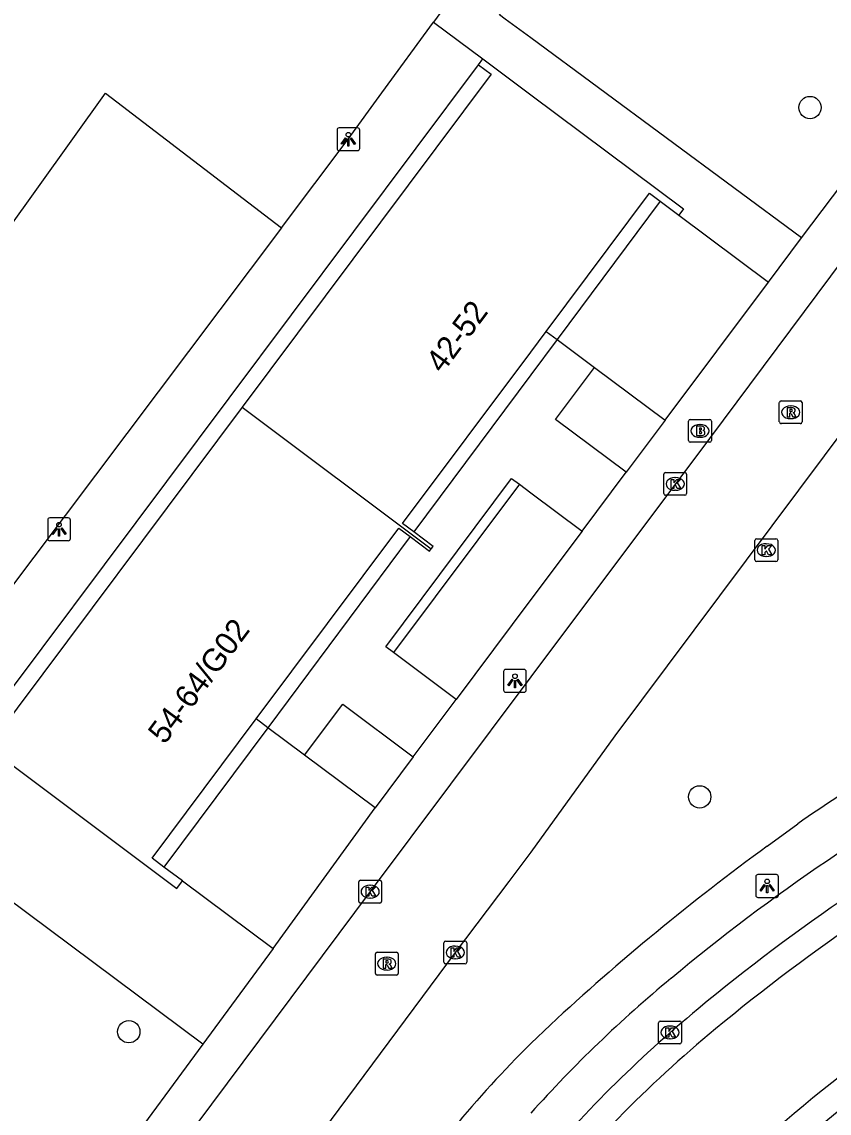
# Model space of a CAD drawing. Extents: x 160026 to 161302, y 384757 to 385701.
# Drawn here: x 160477.69 to 160513.08, y 385187.88 to 385235.75 of the extents above; entities that cross this region are included whole.
import ezdxf

# ---------------------------------------------------------------- set-up
doc = ezdxf.new("R2010")
doc.units = 0
for name, color, linetype in [('IMGEO_Boom', 7, 'Continuous'), ('IMGEO_Brandkraan', 7, 'Continuous'), ('IMGEO_Groenvoorziening', 7, 'Continuous'), ('IMGEO_Haag', 7, 'Continuous'), ('IMGEO_Kolk', 7, 'Continuous'), ('IMGEO_Lichtpunt', 7, 'Continuous'), ('IMGEO_Pand', 7, 'Continuous'), ('IMGEO_Pand_nummerreeks', 7, 'Continuous'), ('IMGEO_Rijbaan_lokaal_open', 7, 'Continuous'), ('IMGEO_Rioolput', 7, 'Continuous'), ('IMGEO_Voetpad_open', 7, 'Continuous')]:
    doc.layers.add(name, color=color, linetype=linetype)

msp = doc.modelspace()

# ---------------------------------------------------------------- linework, layer by layer
at = {"layer": 'IMGEO_Boom'}
for centre in [(160512.24, 385231.991), (160507.406, 385201.754), (160482.378, 385191.451)]:
    msp.add_circle(centre, 0.489, dxfattribs=at)
at = {"layer": 'IMGEO_Brandkraan'}
for p, q in [((160506.992, 385218.308), (160507.844, 385218.308)), ((160506.917, 385217.382), (160506.917, 385218.234)), ((160507.405, 385218.088), (160507.43, 385218.088)), ((160507.918, 385218.234), (160507.918, 385217.382)), ((160507.844, 385217.308), (160506.992, 385217.308)), ((160507.428, 385217.528), (160507.403, 385217.528))]:
    msp.add_line(p, q, dxfattribs=at)
for points in [[(160506.992, 385218.308), (160507.844, 385218.308)], [(160506.917, 385217.382), (160506.917, 385218.234)], [(160507.265, 385218.008), (160507.265, 385217.608), (160507.478, 385217.608)], [(160507.496, 385218.008), (160507.265, 385218.008)], [(160507.444, 385217.927), (160507.39, 385217.927), (160507.39, 385217.851)], [(160507.39, 385217.851), (160507.443, 385217.851)], [(160507.918, 385218.234), (160507.918, 385217.382)], [(160507.844, 385217.308), (160506.992, 385217.308)], [(160507.452, 385217.775), (160507.39, 385217.775), (160507.39, 385217.694)], [(160507.39, 385217.694), (160507.452, 385217.694)]]:
    msp.add_lwpolyline(points, dxfattribs=at)
for centre, radius, start, end in [((160506.994, 385218.232), 0.0765, 91.552, 178.448), ((160506.994, 385218.232), 0.0765, 91.552, 178.448), ((160507.842, 385218.232), 0.0765, 1.552, 88.448), ((160507.842, 385218.232), 0.0765, 1.552, 88.448), ((160507.445, 385217.889), 0.0379, 267.8285, 90.9355), ((160507.5, 385217.863), 0.145, 59.4692, 91.5367), ((160507.525, 385217.91), 0.0922, 285.5137, 58.1501), ((160507.53, 385217.718), 0.105, 301.3115, 78.989), ((160506.994, 385217.384), 0.0765, 181.552, 268.448), ((160506.994, 385217.384), 0.0765, 181.552, 268.448), ((160507.453, 385217.734), 0.0404, 269.8759, 90.5077), ((160507.484, 385217.859), 0.251, 268.6676, 293.5347), ((160507.842, 385217.384), 0.0765, 271.552, 358.448), ((160507.842, 385217.384), 0.0765, 271.552, 358.448)]:
    msp.add_arc(centre, radius, start, end, dxfattribs=at)
for centre, major_axis, ratio, start_param, end_param in [((160507.404, 385217.808), (-0.387, 0.002), 0.722429, 4.712389, 7.853982), ((160507.429, 385217.808), (-0.39, 0.002), 0.717154, 1.570796, 4.712389)]:
    msp.add_ellipse(centre, major_axis=major_axis, ratio=ratio, start_param=start_param, end_param=end_param, dxfattribs=at)
at = {"layer": 'IMGEO_Groenvoorziening'}
msp.add_lwpolyline([(160468.159, 385214.178), (160481.35, 385232.629), (160489.078, 385226.722)], dxfattribs=at)
at = {"layer": 'IMGEO_Haag'}
for points in [[(160499.5, 385215.467), (160493.98, 385208.083)], [(160485.617, 385190.899), (160475.997, 385198.091), (160474.75, 385196.469)]]:
    msp.add_lwpolyline(points, dxfattribs=at)
at = {"layer": 'IMGEO_Kolk'}
for p, q in [((160505.83, 385215.056), (160505.83, 385215.908)), ((160505.905, 385215.982), (160506.757, 385215.982)), ((160506.831, 385215.908), (160506.831, 385215.056)), ((160506.318, 385215.762), (160506.343, 385215.762)), ((160506.757, 385214.982), (160505.905, 385214.982)), ((160506.341, 385215.202), (160506.316, 385215.202)), ((160509.822, 385212.15), (160509.822, 385213.002)), ((160509.897, 385213.076), (160510.749, 385213.076)), ((160510.823, 385213.002), (160510.823, 385212.15)), ((160510.31, 385212.856), (160510.335, 385212.856)), ((160510.749, 385212.076), (160509.897, 385212.076)), ((160510.333, 385212.296), (160510.308, 385212.296)), ((160492.458, 385197.168), (160492.458, 385198.02)), ((160492.533, 385198.094), (160493.385, 385198.094)), ((160492.946, 385197.874), (160492.971, 385197.874)), ((160493.459, 385198.02), (160493.459, 385197.168)), ((160492.969, 385197.314), (160492.944, 385197.314)), ((160493.385, 385197.094), (160492.533, 385197.094)), ((160496.189, 385194.502), (160496.189, 385195.354)), ((160496.264, 385195.428), (160497.116, 385195.428)), ((160497.19, 385195.354), (160497.19, 385194.502)), ((160496.677, 385195.208), (160496.702, 385195.208)), ((160497.116, 385194.428), (160496.264, 385194.428)), ((160496.7, 385194.648), (160496.675, 385194.648)), ((160505.601, 385190.993), (160505.601, 385191.845)), ((160505.676, 385191.919), (160506.528, 385191.919)), ((160506.089, 385191.699), (160506.114, 385191.699)), ((160506.602, 385191.845), (160506.602, 385190.993)), ((160506.112, 385191.139), (160506.087, 385191.139)), ((160506.528, 385190.919), (160505.676, 385190.919))]:
    msp.add_line(p, q, dxfattribs=at)
for points in [[(160505.83, 385215.056), (160505.83, 385215.908)], [(160505.905, 385215.982), (160506.757, 385215.982)], [(160506.831, 385215.908), (160506.831, 385215.056)], [(160506.151, 385215.682), (160506.274, 385215.682), (160506.274, 385215.531), (160506.404, 385215.682), (160506.568, 385215.682), (160506.422, 385215.531), (160506.575, 385215.282), (160506.423, 385215.282), (160506.338, 385215.446), (160506.274, 385215.379), (160506.274, 385215.282), (160506.151, 385215.282), (160506.151, 385215.682)], [(160506.757, 385214.982), (160505.905, 385214.982)], [(160509.822, 385212.15), (160509.822, 385213.002)], [(160509.897, 385213.076), (160510.749, 385213.076)], [(160510.823, 385213.002), (160510.823, 385212.15)], [(160510.143, 385212.776), (160510.266, 385212.776), (160510.266, 385212.625), (160510.396, 385212.776), (160510.56, 385212.776), (160510.414, 385212.625), (160510.567, 385212.376), (160510.415, 385212.376), (160510.33, 385212.54), (160510.266, 385212.473), (160510.266, 385212.376), (160510.143, 385212.376), (160510.143, 385212.776)], [(160510.749, 385212.076), (160509.897, 385212.076)], [(160492.458, 385197.168), (160492.458, 385198.02)], [(160492.533, 385198.094), (160493.385, 385198.094)], [(160492.779, 385197.794), (160492.902, 385197.794), (160492.902, 385197.643), (160493.032, 385197.794), (160493.196, 385197.794), (160493.05, 385197.643), (160493.203, 385197.394), (160493.051, 385197.394), (160492.966, 385197.558), (160492.902, 385197.491), (160492.902, 385197.394), (160492.779, 385197.394), (160492.779, 385197.794)], [(160493.459, 385198.02), (160493.459, 385197.168)], [(160493.385, 385197.094), (160492.533, 385197.094)], [(160496.189, 385194.502), (160496.189, 385195.354)], [(160496.264, 385195.428), (160497.116, 385195.428)], [(160497.19, 385195.354), (160497.19, 385194.502)], [(160496.51, 385195.128), (160496.633, 385195.128), (160496.633, 385194.977), (160496.763, 385195.128), (160496.927, 385195.128), (160496.781, 385194.977), (160496.934, 385194.728), (160496.782, 385194.728), (160496.697, 385194.892), (160496.633, 385194.825), (160496.633, 385194.728), (160496.51, 385194.728), (160496.51, 385195.128)], [(160497.116, 385194.428), (160496.264, 385194.428)], [(160505.601, 385190.993), (160505.601, 385191.845)], [(160505.676, 385191.919), (160506.528, 385191.919)], [(160505.922, 385191.619), (160506.045, 385191.619), (160506.045, 385191.468), (160506.175, 385191.619), (160506.339, 385191.619), (160506.193, 385191.468), (160506.346, 385191.219), (160506.194, 385191.219), (160506.109, 385191.383), (160506.045, 385191.316), (160506.045, 385191.219), (160505.922, 385191.219), (160505.922, 385191.619)], [(160506.602, 385191.845), (160506.602, 385190.993)], [(160506.528, 385190.919), (160505.676, 385190.919)]]:
    msp.add_lwpolyline(points, dxfattribs=at)
for centre, start, end in [((160505.907, 385215.906), 91.552, 178.448), ((160505.907, 385215.906), 91.552, 178.448), ((160506.755, 385215.906), 1.552, 88.448), ((160506.755, 385215.906), 1.552, 88.448), ((160505.907, 385215.058), 181.552, 268.448), ((160505.907, 385215.058), 181.552, 268.448), ((160506.755, 385215.058), 271.552, 358.448), ((160506.755, 385215.058), 271.552, 358.448), ((160509.899, 385213), 91.552, 178.448), ((160509.899, 385213), 91.552, 178.448), ((160510.747, 385213), 1.552, 88.448), ((160510.747, 385213), 1.552, 88.448), ((160509.899, 385212.152), 181.552, 268.448), ((160509.899, 385212.152), 181.552, 268.448), ((160510.747, 385212.152), 271.552, 358.448), ((160510.747, 385212.152), 271.552, 358.448), ((160492.535, 385198.018), 91.552, 178.448), ((160492.535, 385198.018), 91.552, 178.448), ((160493.383, 385198.018), 1.552, 88.448), ((160493.383, 385198.018), 1.552, 88.448), ((160492.535, 385197.17), 181.552, 268.448), ((160492.535, 385197.17), 181.552, 268.448), ((160493.383, 385197.17), 271.552, 358.448), ((160493.383, 385197.17), 271.552, 358.448), ((160496.266, 385195.352), 91.552, 178.448), ((160496.266, 385195.352), 91.552, 178.448), ((160497.114, 385195.352), 1.552, 88.448), ((160497.114, 385195.352), 1.552, 88.448), ((160496.266, 385194.504), 181.552, 268.448), ((160496.266, 385194.504), 181.552, 268.448), ((160497.114, 385194.504), 271.552, 358.448), ((160497.114, 385194.504), 271.552, 358.448), ((160505.678, 385191.843), 91.552, 178.448), ((160505.678, 385191.843), 91.552, 178.448), ((160506.526, 385191.843), 1.552, 88.448), ((160506.526, 385191.843), 1.552, 88.448), ((160505.678, 385190.995), 181.552, 268.448), ((160505.678, 385190.995), 181.552, 268.448), ((160506.526, 385190.995), 271.552, 358.448), ((160506.526, 385190.995), 271.552, 358.448)]:
    msp.add_arc(centre, 0.0765, start, end, dxfattribs=at)
for centre, major_axis, ratio, start_param, end_param in [((160506.317, 385215.482), (-0.387, 0.002), 0.722429, 4.712389, 7.853982), ((160506.342, 385215.482), (-0.39, 0.002), 0.717154, 1.570796, 4.712389), ((160510.309, 385212.576), (-0.387, 0.002), 0.722429, 4.712389, 7.853982), ((160510.334, 385212.576), (-0.39, 0.002), 0.717154, 1.570796, 4.712389), ((160492.945, 385197.594), (-0.387, 0.002), 0.722429, 4.712389, 7.853982), ((160492.97, 385197.594), (-0.39, 0.002), 0.717154, 1.570796, 4.712389), ((160496.676, 385194.928), (-0.387, 0.002), 0.722429, 4.712389, 7.853982), ((160496.701, 385194.928), (-0.39, 0.002), 0.717154, 1.570796, 4.712389), ((160506.088, 385191.419), (-0.387, 0.002), 0.722429, 4.712389, 7.853982), ((160506.113, 385191.419), (-0.39, 0.002), 0.717154, 1.570796, 4.712389)]:
    msp.add_ellipse(centre, major_axis=major_axis, ratio=ratio, start_param=start_param, end_param=end_param, dxfattribs=at)
at = {"layer": 'IMGEO_Lichtpunt'}
for p, q in [((160491.506, 385231.005), (160491.506, 385230.198)), ((160491.506, 385231.005), (160491.506, 385230.198)), ((160492.408, 385231.1), (160491.6, 385231.1)), ((160492.408, 385231.1), (160491.6, 385231.1)), ((160492.502, 385230.198), (160492.502, 385231.005)), ((160492.502, 385230.198), (160492.502, 385231.005)), ((160491.6, 385230.104), (160492.408, 385230.104)), ((160491.6, 385230.104), (160492.408, 385230.104)), ((160479.724, 385213.989), (160478.916, 385213.989)), ((160479.724, 385213.989), (160478.916, 385213.989)), ((160478.822, 385213.894), (160478.822, 385213.087)), ((160478.822, 385213.894), (160478.822, 385213.087)), ((160479.818, 385213.087), (160479.818, 385213.894)), ((160479.818, 385213.087), (160479.818, 385213.894)), ((160478.916, 385212.993), (160479.724, 385212.993)), ((160478.916, 385212.993), (160479.724, 385212.993)), ((160499.708, 385207.342), (160498.9, 385207.342)), ((160499.708, 385207.342), (160498.9, 385207.342)), ((160498.806, 385207.247), (160498.806, 385206.44)), ((160498.806, 385207.247), (160498.806, 385206.44)), ((160499.802, 385206.44), (160499.802, 385207.247)), ((160499.802, 385206.44), (160499.802, 385207.247)), ((160498.9, 385206.346), (160499.708, 385206.346)), ((160498.9, 385206.346), (160499.708, 385206.346)), ((160509.862, 385198.248), (160509.862, 385197.441)), ((160509.862, 385198.248), (160509.862, 385197.441)), ((160510.764, 385198.343), (160509.956, 385198.343)), ((160510.764, 385198.343), (160509.956, 385198.343)), ((160510.858, 385197.441), (160510.858, 385198.248)), ((160510.858, 385197.441), (160510.858, 385198.248)), ((160509.956, 385197.347), (160510.764, 385197.347)), ((160509.956, 385197.347), (160510.764, 385197.347))]:
    msp.add_line(p, q, dxfattribs=at)
for points in [[(160491.88, 385230.669), (160491.919, 385230.641), (160491.731, 385230.379), (160491.693, 385230.406), (160491.88, 385230.669)], [(160491.982, 385230.621), (160492.029, 385230.621), (160492.029, 385230.299), (160491.982, 385230.299), (160491.982, 385230.621)], [(160492.092, 385230.641), (160492.13, 385230.668), (160492.317, 385230.406), (160492.278, 385230.378), (160492.092, 385230.641)], [(160479.196, 385213.558), (160479.235, 385213.53), (160479.047, 385213.268), (160479.009, 385213.295), (160479.196, 385213.558)], [(160479.298, 385213.51), (160479.345, 385213.51), (160479.345, 385213.188), (160479.298, 385213.188), (160479.298, 385213.51)], [(160479.408, 385213.53), (160479.446, 385213.557), (160479.633, 385213.295), (160479.594, 385213.267), (160479.408, 385213.53)], [(160499.18, 385206.911), (160499.219, 385206.883), (160499.031, 385206.621), (160498.993, 385206.648), (160499.18, 385206.911)], [(160499.282, 385206.863), (160499.329, 385206.863), (160499.329, 385206.541), (160499.282, 385206.541), (160499.282, 385206.863)], [(160499.392, 385206.883), (160499.43, 385206.91), (160499.617, 385206.648), (160499.578, 385206.62), (160499.392, 385206.883)], [(160510.236, 385197.912), (160510.275, 385197.884), (160510.087, 385197.622), (160510.049, 385197.649), (160510.236, 385197.912)], [(160510.338, 385197.864), (160510.385, 385197.864), (160510.385, 385197.542), (160510.338, 385197.542), (160510.338, 385197.864)], [(160510.448, 385197.884), (160510.486, 385197.911), (160510.673, 385197.649), (160510.634, 385197.621), (160510.448, 385197.884)]]:
    msp.add_lwpolyline(points, dxfattribs=at)
for centre in [(160492.005, 385230.803), (160479.321, 385213.692), (160499.305, 385207.045), (160510.361, 385198.046)]:
    msp.add_circle(centre, 0.0994, dxfattribs=at)
for centre, start, end in [((160491.6, 385231.005), 90, 180), ((160491.6, 385231.005), 90, 180), ((160492.408, 385231.005), 0, 90), ((160492.408, 385231.005), 0, 90), ((160491.6, 385230.198), 180, 270), ((160491.6, 385230.198), 180, 270), ((160492.408, 385230.198), 270, 0), ((160492.408, 385230.198), 270, 360), ((160478.916, 385213.894), 90, 180), ((160478.916, 385213.894), 90, 180), ((160479.724, 385213.894), 0, 90), ((160479.724, 385213.894), 0, 90), ((160478.916, 385213.087), 180, 270), ((160478.916, 385213.087), 180, 270), ((160479.724, 385213.087), 270, 0), ((160479.724, 385213.087), 270, 360), ((160498.9, 385207.247), 90, 180), ((160498.9, 385207.247), 90, 180), ((160499.708, 385207.247), 0, 90), ((160499.708, 385207.247), 0, 90), ((160498.9, 385206.44), 180, 270), ((160498.9, 385206.44), 180, 270), ((160499.708, 385206.44), 270, 0), ((160499.708, 385206.44), 270, 360), ((160509.956, 385198.248), 90, 180), ((160509.956, 385198.248), 90, 180), ((160510.764, 385198.248), 0, 90), ((160510.764, 385198.248), 0, 90), ((160509.956, 385197.441), 180, 270), ((160509.956, 385197.441), 180, 270), ((160510.764, 385197.441), 270, 0), ((160510.764, 385197.441), 270, 360)]:
    msp.add_arc(centre, 0.0946, start, end, dxfattribs=at)
at = {"layer": 'IMGEO_Pand'}
for points in [[(160497.703, 385233.866), (160497.896, 385234.123)], [(160497.896, 385234.123), (160500, 385232.551), (160506.692, 385227.547), (160506.486, 385227.271)], [(160497.703, 385233.866), (160498.26, 385233.45), (160487.341, 385218.845)], [(160500.676, 385222.173), (160505.205, 385228.229), (160505.665, 385227.885)], [(160505.665, 385227.885), (160506.486, 385227.271)], [(160494.866, 385213.374), (160494.374, 385213.742), (160500, 385221.268), (160500.676, 385222.173)], [(160487.341, 385218.845), (160476.395, 385204.204), (160475.837, 385204.622)], [(160487.341, 385218.845), (160495.64, 385212.639)], [(160487.957, 385205.171), (160494.218, 385213.546), (160494.717, 385213.173)], [(160494.717, 385213.173), (160495.565, 385212.539), (160495.64, 385212.639)], [(160495.64, 385212.639), (160495.715, 385212.74), (160494.866, 385213.374)], [(160483.921, 385198.677), (160483.396, 385199.07), (160487.957, 385205.171)], [(160475.636, 385204.353), (160484.481, 385197.741), (160484.729, 385198.073)], [(160484.729, 385198.073), (160483.921, 385198.677)]]:
    msp.add_lwpolyline(points, dxfattribs=at)
at = {"layer": 'IMGEO_Rijbaan_lokaal_open'}
for points in [[(160534.696, 385253.556), (160532.047, 385250), (160507.827, 385217.481), (160500, 385207.013), (160492.96, 385197.597), (160479.05, 385178.94), (160478.747, 385178.564)], [(160505.665, 385227.885), (160501.15, 385221.819)], [(160506.486, 385227.271), (160510.414, 385224.335)], [(160505.886, 385218.278), (160510.414, 385224.335)], [(160500.676, 385222.173), (160501.15, 385221.819)], [(160501.15, 385221.819), (160502.798, 385220.586)], [(160515.782, 385220.64), (160514.031, 385218.275), (160503.68, 385204.434), (160500, 385199.324), (160499.031, 385198.037), (160496.692, 385194.932), (160483.238, 385176.808)], [(160502.798, 385220.586), (160505.886, 385218.278)], [(160488.471, 385204.787), (160487.957, 385205.171)], [(160488.471, 385204.787), (160483.921, 385198.677)], [(160490.085, 385203.58), (160488.471, 385204.787)], [(160493.173, 385201.272), (160490.085, 385203.58)], [(160488.705, 385195.106), (160493.173, 385201.272)], [(160484.729, 385198.073), (160488.705, 385195.106)]]:
    msp.add_lwpolyline(points, dxfattribs=at)
for centre, radius, start, end in [((160561.785, 385127.006), 85.137, 118.47521, 129.76105), ((160562.036, 385126.591), 84.451, 118.47544, 129.694), ((160542.648, 385149.659), 55.483, 129.5311, 140.234), ((160551.686, 385140.56), 62.037, 123.39036, 139.22931), ((160542.842, 385149.481), 54.579, 129.5368, 141.7157), ((160551.43, 385141.061), 60.334, 123.54198, 139.53806)]:
    msp.add_arc(centre, radius, start, end, dxfattribs=at)
at = {"layer": 'IMGEO_Rioolput'}
for p, q in [((160510.895, 385218.199), (160510.895, 385219.051)), ((160510.97, 385219.125), (160511.822, 385219.125)), ((160511.383, 385218.905), (160511.408, 385218.905)), ((160511.896, 385219.051), (160511.896, 385218.199)), ((160511.406, 385218.345), (160511.381, 385218.345)), ((160511.822, 385218.125), (160510.97, 385218.125)), ((160493.187, 385194.013), (160493.187, 385194.865)), ((160493.262, 385194.939), (160494.114, 385194.939)), ((160494.188, 385194.865), (160494.188, 385194.013)), ((160493.675, 385194.719), (160493.7, 385194.719)), ((160494.114, 385193.939), (160493.262, 385193.939)), ((160493.698, 385194.159), (160493.673, 385194.159))]:
    msp.add_line(p, q, dxfattribs=at)
for points in [[(160510.895, 385218.199), (160510.895, 385219.051)], [(160510.97, 385219.125), (160511.822, 385219.125)], [(160511.484, 385218.823), (160511.232, 385218.825), (160511.232, 385218.425)], [(160511.41, 385218.744), (160511.356, 385218.744), (160511.356, 385218.663)], [(160511.896, 385219.051), (160511.896, 385218.199)], [(160511.232, 385218.425), (160511.356, 385218.425), (160511.356, 385218.587), (160511.367, 385218.587)], [(160511.356, 385218.663), (160511.408, 385218.663)], [(160511.414, 385218.558), (160511.485, 385218.425), (160511.625, 385218.425), (160511.56, 385218.551)], [(160511.822, 385218.125), (160510.97, 385218.125)], [(160493.187, 385194.013), (160493.187, 385194.865)], [(160493.262, 385194.939), (160494.114, 385194.939)], [(160494.188, 385194.865), (160494.188, 385194.013)], [(160493.776, 385194.637), (160493.524, 385194.639), (160493.524, 385194.239)], [(160493.524, 385194.239), (160493.648, 385194.239), (160493.648, 385194.401), (160493.659, 385194.401)], [(160493.702, 385194.558), (160493.648, 385194.558), (160493.648, 385194.477)], [(160493.648, 385194.477), (160493.7, 385194.477)], [(160493.706, 385194.372), (160493.777, 385194.239), (160493.917, 385194.239), (160493.852, 385194.365)], [(160494.114, 385193.939), (160493.262, 385193.939)]]:
    msp.add_lwpolyline(points, dxfattribs=at)
for centre, radius, start, end in [((160510.972, 385219.049), 0.0765, 91.552, 178.448), ((160510.972, 385219.049), 0.0765, 91.552, 178.448), ((160511.416, 385218.648), 0.0964, 77.0061, 93.1865), ((160511.483, 385218.713), 0.109, 350.3612, 89.416), ((160511.82, 385219.049), 0.0765, 1.552, 88.448), ((160511.82, 385219.049), 0.0765, 1.552, 88.448), ((160511.366, 385218.534), 0.0533, 26.0293, 88.6989), ((160511.392, 385218.852), 0.19, 274.7715, 282.9687), ((160511.43, 385218.705), 0.0378, 276.6634, 79.6772), ((160511.481, 385218.713), 0.112, 277.5842, 350.9817), ((160511.465, 385218.498), 0.108, 29.5134, 73.7905), ((160510.972, 385218.201), 0.0765, 181.552, 268.448), ((160510.972, 385218.201), 0.0765, 181.552, 268.448), ((160511.82, 385218.201), 0.0765, 271.552, 358.448), ((160511.82, 385218.201), 0.0765, 271.552, 358.448), ((160493.264, 385194.863), 0.0765, 91.552, 178.448), ((160493.264, 385194.863), 0.0765, 91.552, 178.448), ((160494.112, 385194.863), 0.0765, 1.552, 88.448), ((160494.112, 385194.863), 0.0765, 1.552, 88.448), ((160493.658, 385194.348), 0.0533, 26.0293, 88.6989), ((160493.684, 385194.666), 0.19, 274.7715, 282.9687), ((160493.708, 385194.462), 0.0964, 77.0061, 93.1865), ((160493.722, 385194.519), 0.0378, 276.6634, 79.6772), ((160493.775, 385194.527), 0.109, 350.3612, 89.416), ((160493.773, 385194.527), 0.112, 277.5842, 350.9817), ((160493.757, 385194.312), 0.108, 29.5134, 73.7905), ((160493.264, 385194.015), 0.0765, 181.552, 268.448), ((160493.264, 385194.015), 0.0765, 181.552, 268.448), ((160494.112, 385194.015), 0.0765, 271.552, 358.448), ((160494.112, 385194.015), 0.0765, 271.552, 358.448)]:
    msp.add_arc(centre, radius, start, end, dxfattribs=at)
for centre, major_axis, ratio, start_param, end_param in [((160511.382, 385218.625), (-0.387, 0.002), 0.722429, 4.712389, 7.853982), ((160511.407, 385218.625), (-0.39, 0.002), 0.717154, 1.570796, 4.712389), ((160493.674, 385194.439), (-0.387, 0.002), 0.722429, 4.712389, 7.853982), ((160493.699, 385194.439), (-0.39, 0.002), 0.717154, 1.570796, 4.712389)]:
    msp.add_ellipse(centre, major_axis=major_axis, ratio=ratio, start_param=start_param, end_param=end_param, dxfattribs=at)
at = {"layer": 'IMGEO_Voetpad_open'}
for points in [[(160511.864, 385226.278), (160500, 385235.044), (160498.881, 385235.87), (160498.625, 385236.059), (160503.898, 385243.363), (160504.171, 385243.163), (160517.353, 385233.53)], [(160498.717, 385239.811), (160495.737, 385235.736)], [(160489.078, 385226.722), (160491.999, 385230.602), (160493.475, 385232.642), (160495.737, 385235.736)], [(160495.737, 385235.736), (160497.896, 385234.123)], [(160475.837, 385204.622), (160497.703, 385233.866)], [(160511.864, 385226.278), (160517.353, 385233.53)], [(160489.078, 385226.722), (160475.491, 385208.676), (160468.159, 385214.178)], [(160510.414, 385224.335), (160511.864, 385226.278)], [(160501.15, 385221.819), (160500, 385220.274), (160494.866, 385213.374)], [(160504.178, 385215.993), (160501.09, 385218.302), (160502.798, 385220.586)], [(160505.886, 385218.278), (160504.178, 385215.993)], [(160502.248, 385213.412), (160504.178, 385215.993)], [(160493.98, 385208.083), (160493.64, 385208.337), (160499.16, 385215.721), (160499.5, 385215.467)], [(160499.5, 385215.467), (160500, 385215.093), (160502.248, 385213.412)], [(160494.717, 385213.173), (160488.471, 385204.787)], [(160502.248, 385213.412), (160500, 385210.405), (160496.728, 385206.028)], [(160496.728, 385206.028), (160493.98, 385208.083)], [(160494.843, 385203.506), (160496.728, 385206.028)], [(160490.085, 385203.58), (160491.755, 385205.815), (160494.843, 385203.506)], [(160494.843, 385203.506), (160493.173, 385201.272)], [(160510.362, 385199.593), (160511.702, 385200.57)], [(160488.705, 385195.106), (160485.617, 385190.899)], [(160500, 385190.931), (160500.857, 385191.756)], [(160485.617, 385190.899), (160478.234, 385180.842)]]:
    msp.add_lwpolyline(points, dxfattribs=at)
for centre, radius, start, end in [((160547.663, 385149.143), 62.753, 116.77697, 124.96409), ((160561.501, 385127.452), 86.397, 118.45575, 129.84389), ((160573.779, 385112.995), 107.335, 126.21622, 132.79586), ((160542.408, 385149.913), 56.92, 129.5741, 138.1636), ((160533.712, 385156.749), 48.009, 134.6037, 146.6079), ((160551.498, 385140.762), 58.815, 123.47663, 139.18295), ((160545.856, 385148.537), 46.607, 120.9274, 140.5514)]:
    msp.add_arc(centre, radius, start, end, dxfattribs=at)

# ---------------------------------------------------------------- texts
at = {"layer": 'IMGEO_Pand_nummerreeks'}
for s, rotation, p in [('42-52', 53.2169, (160496.123, 385220.29)), ('54-64/G02', 53.2189, (160483.947, 385204.016))]:
    msp.add_text(s, height=1, rotation=rotation, dxfattribs=at).set_placement(p)

doc.saveas('drawing.dxf')
